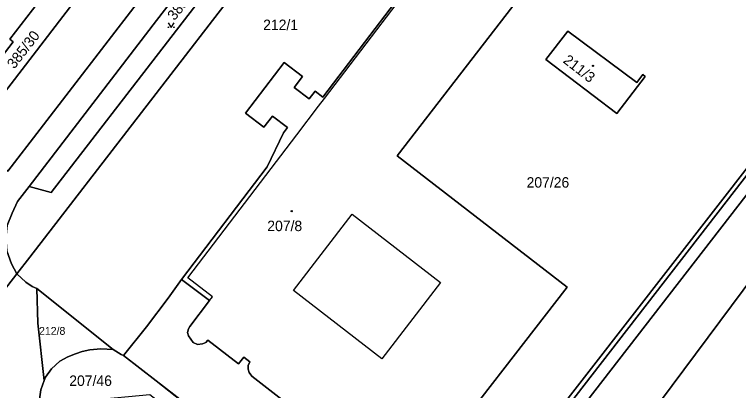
# Model space of a CAD drawing. Extents: x -598934 to -598196, y -1162208 to -1161502.
# Drawn here: x -598804.1 to -598686.2, y -1162077.8 to -1162016.6 of the extents above; entities that cross this region are included whole.
import ezdxf

# ---------------------------------------------------------------- set-up
doc = ezdxf.new("R2010")
doc.units = 0
for name, color, linetype in [('KN_CAR_KR', 7, 'Continuous'), ('KN_KULTURY', 7, 'Continuous'), ('KN_PARC_CIS_POZ', 7, 'Continuous'), ('KN_PARC_CIS_STAV', 7, 'Continuous'), ('KN_PARC_PLOCHA', 7, 'Continuous'), ('parcely_l', 7, 'Continuous')]:
    doc.layers.add(name, color=color, linetype=linetype)

msp = doc.modelspace()

# ---------------------------------------------------------------- linework, layer by layer
at = {"layer": 'KN_CAR_KR'}
for points in [[(-598753.65, -1162030.23), (-598734.99, -1162005.76)], [(-598754.61, -1162031.49), (-598753.65, -1162030.23)], [(-598758.16, -1162036.14), (-598754.61, -1162031.49)], [(-598775.92, -1162059.44), (-598758.16, -1162036.14)], [(-598758.7, -1162061.5), (-598749.12, -1162049.1)], [(-598749.12, -1162049.1), (-598734.72, -1162060.22)], [(-598771.86, -1162062.54), (-598775.92, -1162059.44)], [(-598734.72, -1162060.22), (-598744.31, -1162072.65)], [(-598744.31, -1162072.65), (-598758.7, -1162061.5)], [(-598772.36, -1162063.16), (-598771.86, -1162062.54)]]:
    msp.add_lwpolyline(points, dxfattribs=at)
at = {"layer": 'KN_KULTURY'}
msp.add_lwpolyline([(-598779.12, -1162017.96), (-598778.62, -1162018.71), (-598778.12, -1162017.96)], dxfattribs=at)
for centre, radius in [((-598779.07, -1162018.66), 0.05), ((-598778.17, -1162018.66), 0.05), ((-598709.9, -1162024.93), 0.09), ((-598709.9, -1162024.93), 0.0398), ((-598758.98, -1162048.6), 0.09), ((-598758.98, -1162048.6), 0.0398)]:
    msp.add_circle(centre, radius, dxfattribs=at)
at = {"layer": 'KN_PARC_PLOCHA'}
for points in [[(-598725.15, -1161938.28), (-598725.73, -1161939.03), (-598784.14, -1162014.75), (-598805.25, -1162042.08), (-598805.73, -1162041.71), (-598824.9, -1162066.06), (-598829.3, -1162071.75), (-598834.62, -1162067.66), (-598830.2, -1162061.93), (-598819.69, -1162047.55), (-598811.67, -1162037.16), (-598811.81, -1162037.05), (-598811.38, -1162036.49), (-598784.24, -1162001.22), (-598731.65, -1161933.61), (-598731.93, -1161933.4), (-598731.03, -1161932.2)], [(-598801.77, -1162044.56), (-598781.01, -1162017.58), (-598751.1, -1161978.85), (-598748.97, -1161979.37), (-598747.68, -1161980.16), (-598779.24, -1162021.04), (-598798.16, -1162045.56)], [(-598811.81, -1162037.05), (-598812.61, -1162036.32), (-598813.4, -1162035.12), (-598813.67, -1162034), (-598813.64, -1162032.95), (-598813.45, -1162031.95), (-598813, -1162031.05), (-598812.41, -1162031.47), (-598804.33, -1162021.01), (-598804.91, -1162020.57), (-598797.52, -1162010.97), (-598794.04, -1162009.21), (-598790.94, -1162007.24), (-598788.46, -1162005.15), (-598786.26, -1162003.29), (-598784.24, -1162001.22), (-598811.38, -1162036.49)], [(-598713.99, -1162019.29), (-598702.78, -1162027.64), (-598701.79, -1162026.37), (-598701.42, -1162026.66), (-598705.99, -1162032.69), (-598717.56, -1162023.91)], [(-598713.99, -1162019.29), (-598717.56, -1162023.91), (-598705.99, -1162032.69), (-598701.42, -1162026.66), (-598701.79, -1162026.37), (-598702.78, -1162027.64)], [(-598665.65, -1162024.98), (-598666.93, -1162026.3), (-598678.92, -1162035.38), (-598679.62, -1162036.03), (-598737.47, -1162110.63), (-598781.08, -1162076.2), (-598737.8, -1162109.67), (-598670.02, -1162022.54)], [(-598668.55, -1162035.34), (-598674.02, -1162044.9), (-598673, -1162045.47), (-598673.6, -1162046.51), (-598674.03, -1162046.15), (-598710.29, -1162094.83), (-598710.79, -1162094.46), (-598717.77, -1162103.75), (-598683.27, -1162115.94), (-598682.6, -1162114.05), (-598663.19, -1162120.99), (-598663.85, -1162122.86), (-598634.84, -1162133.15), (-598632.69, -1162127.23), (-598633.35, -1162126.99), (-598616.44, -1162079.32), (-598616.93, -1162078.93), (-598616.33, -1162077.89), (-598615.31, -1162078.48), (-598609.79, -1162068.96), (-598613.68, -1162066.69), (-598612.54, -1162064.68), (-598663.42, -1162035.55), (-598664.65, -1162037.57)], [(-598668.55, -1162035.34), (-598664.65, -1162037.57), (-598663.42, -1162035.55), (-598612.54, -1162064.68), (-598613.68, -1162066.69), (-598609.79, -1162068.96), (-598615.31, -1162078.48), (-598616.33, -1162077.89), (-598616.93, -1162078.93), (-598616.44, -1162079.32), (-598633.35, -1162126.99), (-598632.69, -1162127.23), (-598634.84, -1162133.15), (-598663.85, -1162122.86), (-598663.19, -1162120.99), (-598682.6, -1162114.05), (-598683.27, -1162115.94), (-598717.77, -1162103.75), (-598710.79, -1162094.46), (-598710.29, -1162094.83), (-598674.03, -1162046.15), (-598673.6, -1162046.51), (-598673, -1162045.47), (-598674.02, -1162044.9)], [(-598788.04, -1162071.12), (-598790.06, -1162071.02), (-598791.84, -1162071.17), (-598793.1, -1162071.45), (-598794.18, -1162071.79), (-598795.46, -1162072.29), (-598796.73, -1162073.02), (-598798.11, -1162074.27), (-598799.07, -1162075.62), (-598799.33, -1162076.17), (-598800.31, -1162066.8), (-598800.48, -1162061.16)]]:
    msp.add_lwpolyline(points, close=True, dxfattribs=at)
for points in [[(-598751.1, -1161978.85), (-598781.01, -1162017.58), (-598801.77, -1162044.56), (-598803.63, -1162047), (-598804.53, -1162048.9), (-598805.35, -1162050.93), (-598805.56, -1162052.94), (-598805.38, -1162055.06), (-598804.64, -1162057.15), (-598803.76, -1162058.8), (-598810.21, -1162067.09), (-598811.85, -1162066.25), (-598812.92, -1162065.98), (-598814.06, -1162065.96), (-598815.09, -1162066.06), (-598816.14, -1162066.58), (-598817.16, -1162067.19), (-598818.73, -1162068.64), (-598819.81, -1162070.09), (-598822.68, -1162067.84), (-598824.9, -1162066.06), (-598805.73, -1162041.71), (-598805.25, -1162042.08), (-598784.14, -1162014.75)], [(-598747.09, -1161985.38), (-598801.66, -1162056.1), (-598803.76, -1162058.8), (-598804.64, -1162057.15), (-598805.38, -1162055.06), (-598805.56, -1162052.94), (-598805.35, -1162050.93), (-598804.53, -1162048.9), (-598803.63, -1162047), (-598801.77, -1162044.56), (-598798.16, -1162045.56), (-598779.24, -1162021.04), (-598747.68, -1161980.16)], [(-598735.27, -1162005.55), (-598753.92, -1162030.01), (-598755.18, -1162029.07), (-598756.14, -1162030.33), (-598758.59, -1162028.46), (-598757.22, -1162026.67), (-598760.2, -1162024.4), (-598766.48, -1162032.63), (-598763.5, -1162034.9), (-598762.13, -1162033.11), (-598759.67, -1162034.99), (-598760.31, -1162035.83), (-598762.99, -1162041.4), (-598776.92, -1162059.69), (-598779.1, -1162062.74), (-598782.65, -1162067.44), (-598786.38, -1162072.1), (-598786.78, -1162071.92), (-598788.04, -1162071.12), (-598800.48, -1162061.16), (-598801.28, -1162060.85), (-598802.27, -1162060.17), (-598803.76, -1162058.8), (-598801.66, -1162056.1), (-598747.09, -1161985.38)], [(-598753.52, -1162084.71), (-598765.48, -1162075.45), (-598765.93, -1162074.83), (-598766.08, -1162074.3), (-598766.06, -1162073.72), (-598765.82, -1162073.1), (-598766.79, -1162072.36), (-598767.62, -1162073.45), (-598772.63, -1162069.6), (-598772.97, -1162069.95), (-598773.49, -1162070.21), (-598774.32, -1162070.28), (-598775.02, -1162069.97), (-598775.78, -1162068.87), (-598775.93, -1162068.33), (-598775.81, -1162067.75), (-598775.56, -1162067.36), (-598772.36, -1162063.16), (-598776.92, -1162059.69), (-598762.99, -1162041.4), (-598760.31, -1162035.83), (-598759.67, -1162034.99), (-598762.13, -1162033.11), (-598763.5, -1162034.9), (-598766.48, -1162032.63), (-598760.2, -1162024.4), (-598757.22, -1162026.67), (-598758.59, -1162028.46), (-598756.14, -1162030.33), (-598755.18, -1162029.07), (-598753.92, -1162030.01), (-598735.27, -1162005.55)], [(-598797.52, -1162010.97), (-598804.91, -1162020.57), (-598804.33, -1162021.01), (-598812.41, -1162031.47), (-598813, -1162031.05), (-598813.45, -1162031.95), (-598813.64, -1162032.95), (-598813.67, -1162034), (-598813.4, -1162035.12), (-598812.61, -1162036.32), (-598811.81, -1162037.05), (-598811.67, -1162037.16), (-598819.69, -1162047.55), (-598830.2, -1162061.93), (-598833.27, -1162059.45), (-598836.77, -1162056.74), (-598840.79, -1162062.93), (-598844.17, -1162060.34), (-598857.64, -1162042.61), (-598873.13, -1162022.24), (-598876.32, -1162018.53), (-598884.71, -1162008.72)], [(-598736.75, -1162090.17), (-598714.12, -1162060.96), (-598741.79, -1162039.6), (-598719.25, -1162010.41)], [(-598719.25, -1162010.41), (-598741.79, -1162039.6), (-598714.12, -1162060.96), (-598736.75, -1162090.17)], [(-598670.02, -1162022.54), (-598737.8, -1162109.67), (-598781.08, -1162076.2), (-598786.38, -1162072.1), (-598782.65, -1162067.44), (-598779.1, -1162062.74), (-598776.92, -1162059.69), (-598772.36, -1162063.16), (-598775.56, -1162067.36), (-598775.81, -1162067.75), (-598775.93, -1162068.33), (-598775.78, -1162068.87), (-598775.02, -1162069.97), (-598774.32, -1162070.28), (-598773.49, -1162070.21), (-598772.97, -1162069.95), (-598772.63, -1162069.6), (-598767.62, -1162073.45), (-598766.79, -1162072.36), (-598765.82, -1162073.1), (-598766.06, -1162073.72), (-598766.08, -1162074.3), (-598765.93, -1162074.83), (-598765.48, -1162075.45), (-598753.52, -1162084.71)], [(-598678.11, -1162037.18), (-598737.16, -1162113.44), (-598737.41, -1162113.25), (-598782.1, -1162078.51), (-598791.36, -1162079.36), (-598796.04, -1162079.79), (-598800, -1162080.15), (-598800.02, -1162078.81), (-598799.87, -1162077.69), (-598799.33, -1162076.17), (-598799.07, -1162075.62), (-598798.11, -1162074.27), (-598796.73, -1162073.02), (-598795.46, -1162072.29), (-598794.18, -1162071.79), (-598793.1, -1162071.45), (-598791.84, -1162071.17), (-598790.06, -1162071.02), (-598788.04, -1162071.12), (-598786.78, -1162071.92), (-598786.38, -1162072.1), (-598781.08, -1162076.2), (-598737.47, -1162110.63), (-598679.62, -1162036.03)], [(-598669.65, -1162137.35), (-598720.2, -1162119.59), (-598725.34, -1162117.61), (-598727.76, -1162120.71), (-598729, -1162119.75), (-598733.46, -1162116.3), (-598737.16, -1162113.44), (-598678.11, -1162037.18)], [(-598810.21, -1162067.09), (-598803.76, -1162058.8), (-598802.27, -1162060.17), (-598801.28, -1162060.85), (-598800.48, -1162061.16), (-598800.31, -1162066.8), (-598799.33, -1162076.17), (-598799.87, -1162077.69), (-598800.02, -1162078.81), (-598800, -1162080.15), (-598800, -1162080.43), (-598799.2, -1162085.99), (-598798.79, -1162088.87), (-598798, -1162088.8), (-598793.58, -1162088.43), (-598792.01, -1162104.4), (-598790.96, -1162115.21), (-598792.54, -1162114.22), (-598796.78, -1162109.19), (-598793.98, -1162137.8), (-598792.14, -1162131.05), (-598789.72, -1162127.94), (-598788.2, -1162142.62)]]:
    msp.add_lwpolyline(points, dxfattribs=at)
at = {"layer": 'parcely_l'}
for points in [[(-598824.9, -1162066.06), (-598805.73, -1162041.71), (-598805.25, -1162042.08), (-598784.14, -1162014.75), (-598725.73, -1161939.03), (-598725.15, -1161938.28)], [(-598801.77, -1162044.56), (-598798.16, -1162045.56), (-598779.24, -1162021.04), (-598747.68, -1161980.16), (-598748.97, -1161979.37), (-598751.1, -1161978.85)], [(-598751.1, -1161978.85), (-598781.01, -1162017.58), (-598801.77, -1162044.56)], [(-598744.94, -1161982.47), (-598747.09, -1161985.38), (-598801.66, -1162056.1), (-598803.76, -1162058.8)], [(-598719.1, -1162010.02), (-598731.48, -1162000.58), (-598731.72, -1162000.9), (-598735.42, -1161998.08), (-598734.05, -1161996.29), (-598737.03, -1161994.01), (-598743.32, -1162002.25), (-598740.33, -1162004.52), (-598738.97, -1162002.74), (-598735.27, -1162005.55), (-598753.92, -1162030.01), (-598755.18, -1162029.07), (-598756.14, -1162030.33), (-598758.59, -1162028.46), (-598757.22, -1162026.67), (-598760.2, -1162024.4), (-598766.48, -1162032.63), (-598763.5, -1162034.9), (-598762.13, -1162033.11), (-598759.67, -1162034.99), (-598760.31, -1162035.83), (-598762.99, -1162041.4), (-598776.92, -1162059.69)], [(-598784.24, -1162001.22), (-598786.26, -1162003.29), (-598788.46, -1162005.15), (-598790.94, -1162007.24), (-598794.04, -1162009.21), (-598797.52, -1162010.97), (-598804.91, -1162020.57), (-598804.33, -1162021.01), (-598812.41, -1162031.47), (-598813, -1162031.05), (-598813.45, -1162031.95), (-598813.64, -1162032.95), (-598813.67, -1162034), (-598813.4, -1162035.12), (-598812.61, -1162036.32), (-598811.81, -1162037.05)], [(-598784.24, -1162001.22), (-598811.38, -1162036.49), (-598811.81, -1162037.05)], [(-598719.25, -1162010.41), (-598741.79, -1162039.6), (-598714.12, -1162060.96), (-598736.75, -1162090.17)], [(-598713.99, -1162019.29), (-598717.56, -1162023.91), (-598705.99, -1162032.69), (-598701.42, -1162026.66), (-598701.79, -1162026.37), (-598702.78, -1162027.64), (-598713.99, -1162019.29)], [(-598670.02, -1162022.54), (-598737.8, -1162109.67), (-598781.08, -1162076.2)], [(-598781.08, -1162076.2), (-598737.47, -1162110.63), (-598679.62, -1162036.03), (-598678.92, -1162035.38), (-598666.93, -1162026.3), (-598665.65, -1162024.98)], [(-598678.11, -1162037.18), (-598737.16, -1162113.44)], [(-598803.76, -1162058.8), (-598804.64, -1162057.15), (-598805.38, -1162055.06), (-598805.56, -1162052.94), (-598805.35, -1162050.93), (-598804.53, -1162048.9), (-598803.63, -1162047), (-598801.77, -1162044.56)], [(-598683.27, -1162115.94), (-598717.77, -1162103.75), (-598710.79, -1162094.46), (-598710.29, -1162094.83), (-598674.03, -1162046.15)], [(-598803.76, -1162058.8), (-598810.21, -1162067.09)], [(-598800.48, -1162061.16), (-598801.28, -1162060.85), (-598802.27, -1162060.17), (-598803.76, -1162058.8)], [(-598776.92, -1162059.69), (-598779.1, -1162062.74), (-598782.65, -1162067.44), (-598786.38, -1162072.1)], [(-598753.52, -1162084.71), (-598765.48, -1162075.45), (-598765.93, -1162074.83), (-598766.08, -1162074.3), (-598766.06, -1162073.72), (-598765.82, -1162073.1), (-598766.79, -1162072.36), (-598767.62, -1162073.45), (-598772.63, -1162069.6), (-598772.97, -1162069.95), (-598773.49, -1162070.21), (-598774.32, -1162070.28), (-598775.02, -1162069.97), (-598775.78, -1162068.87), (-598775.93, -1162068.33), (-598775.81, -1162067.75), (-598775.56, -1162067.36), (-598772.36, -1162063.16), (-598776.92, -1162059.69)], [(-598788.04, -1162071.12), (-598800.48, -1162061.16)], [(-598800.48, -1162061.16), (-598800.31, -1162066.8), (-598799.33, -1162076.17)], [(-598799.33, -1162076.17), (-598799.07, -1162075.62), (-598798.11, -1162074.27), (-598796.73, -1162073.02), (-598795.46, -1162072.29), (-598794.18, -1162071.79), (-598793.1, -1162071.45), (-598791.84, -1162071.17), (-598790.06, -1162071.02), (-598788.04, -1162071.12)], [(-598786.38, -1162072.1), (-598786.78, -1162071.92), (-598788.04, -1162071.12)], [(-598786.38, -1162072.1), (-598781.08, -1162076.2)], [(-598800, -1162080.15), (-598800.02, -1162078.81), (-598799.87, -1162077.69), (-598799.33, -1162076.17)]]:
    msp.add_lwpolyline(points, dxfattribs=at)

# ---------------------------------------------------------------- texts
at = {"layer": 'KN_PARC_CIS_POZ'}
for s, rotation, p in [('385/11', 51.3004, (-598778.07, -1162017.67)), ('385/30', 52.2003, (-598804.17, -1162025.54))]:
    msp.add_text(s, height=1.7, rotation=rotation, dxfattribs=at).set_placement(p)
for s, height, p in [('212/1', 1.7, (-598763.63, -1162019.11)), ('207/26', 1.7, (-598720.72, -1162044.76)), ('212/8', 1.28, (-598800.14, -1162068.72)), ('207/46', 1.7, (-598795.22, -1162077.04))]:
    msp.add_text(s, height=height, dxfattribs=at).set_placement(p)
at = {"layer": 'KN_PARC_CIS_STAV'}
msp.add_text('211/3', height=1.7, rotation=322.2003, dxfattribs=at).set_placement((-598714.9, -1162024.3))
msp.add_text('207/8', height=1.7, dxfattribs=at).set_placement((-598762.96, -1162051.84))

doc.saveas('drawing.dxf')
